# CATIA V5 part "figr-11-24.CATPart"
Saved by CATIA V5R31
Part number: Part1
Bounding box of the stored display mesh (mm): x -89.703 to 75.958, y -127.286 to 108.862, z -26.487 to 19.815
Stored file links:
  D:\PROJECTS\Project 2021\US EDITION\CATIA V5 6R 2021\Resources\Part Files\c11_catia_v5_6r2021_prt\figr-11-24.CATPart
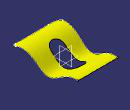
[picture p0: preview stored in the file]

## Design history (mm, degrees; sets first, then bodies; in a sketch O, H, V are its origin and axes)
Set1
  Extrude1: Element1 Sketch3, Lim1 86, Lim2 94, Direction yz-plane
  Sketch1 on xy-plane, origin (0, 0, 0), H (1, 0, 0), V (0, 1, 0)
    line L1 (64.3059, 108.8616) -> (75.9293, -106.0218)
    arc A1 centre (55.7837, -107.1115) radius 20.175 from (75.9293, -106.0218) to (55.7837, -127.2865) cw
    line L2 (55.7837, -127.2865) -> (-64.7868, -127.2865)
    arc A2 centre (-64.7868, -102.3613) radius 24.9252 from (-64.7868, -127.2865) to (-89.6873, -101.2501) cw
    line L3 (-89.6873, -101.2501) -> (-80.3115, 108.8616)
    line L4 (-80.3115, 108.8616) -> (64.3059, 108.8616)
    tangency: A1 L1, A2 L2, A2 L3, A1 L2
    horizontal: L2 H, L4 H
  Extrude2: Element1 Sketch1, Lim1 86, Lim2 94, Direction xy-plane
  Split1: ToCut Extrude1, Cutting Extrude2
  Sketch2 on xy-plane, origin (0, 0, 0), H (1, 0, 0), V (0, 1, 0)
    construction line L1 (-11.3849, 28.4134) -> (-11.3849, -36.9379)
    line L2 (12.8382, 28.4134) -> (12.8382, -36.9379)
    line L3 (-35.608, -36.9379) -> (-35.608, 28.4134)
    arc A1 centre (-11.3849, -36.9379) radius 24.2231 from (12.8382, -36.9379) to (-35.608, -36.9379) cw
    arc A2 centre (-11.3849, 28.4134) radius 24.2231 from (-35.608, 28.4134) to (12.8382, 28.4134) cw
    vertical: L1 V
    tangency: A1 L2, A2 L2, A1 L3, A2 L3
    parallelism: L1 L2
  Extrude3: Element1 Sketch2, Lim1 86, Lim2 94, Direction xy-plane
  Split2: ToCut Split1, Cutting Extrude3
  Boundary1: Boundary edge of Split2, Support Split2
Body1 (main body)
  Sketch3 on yz-plane, origin (0, 0, 0), H (0, 1, 0), V (0, 0, 1)
    spline S1 through (-130.9721, 0) (-85.5087, 19.8151) (-38.0512, 0) (0, -25.6483) (60.0541, -1.7202) (134.7951, -4.3868)
    point P1 (-130.9721, 0)
    point P2 (-38.0512, 0)
    point P3 (0, -25.6483)
    coincidence: P1 H, P2 H, P3 V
